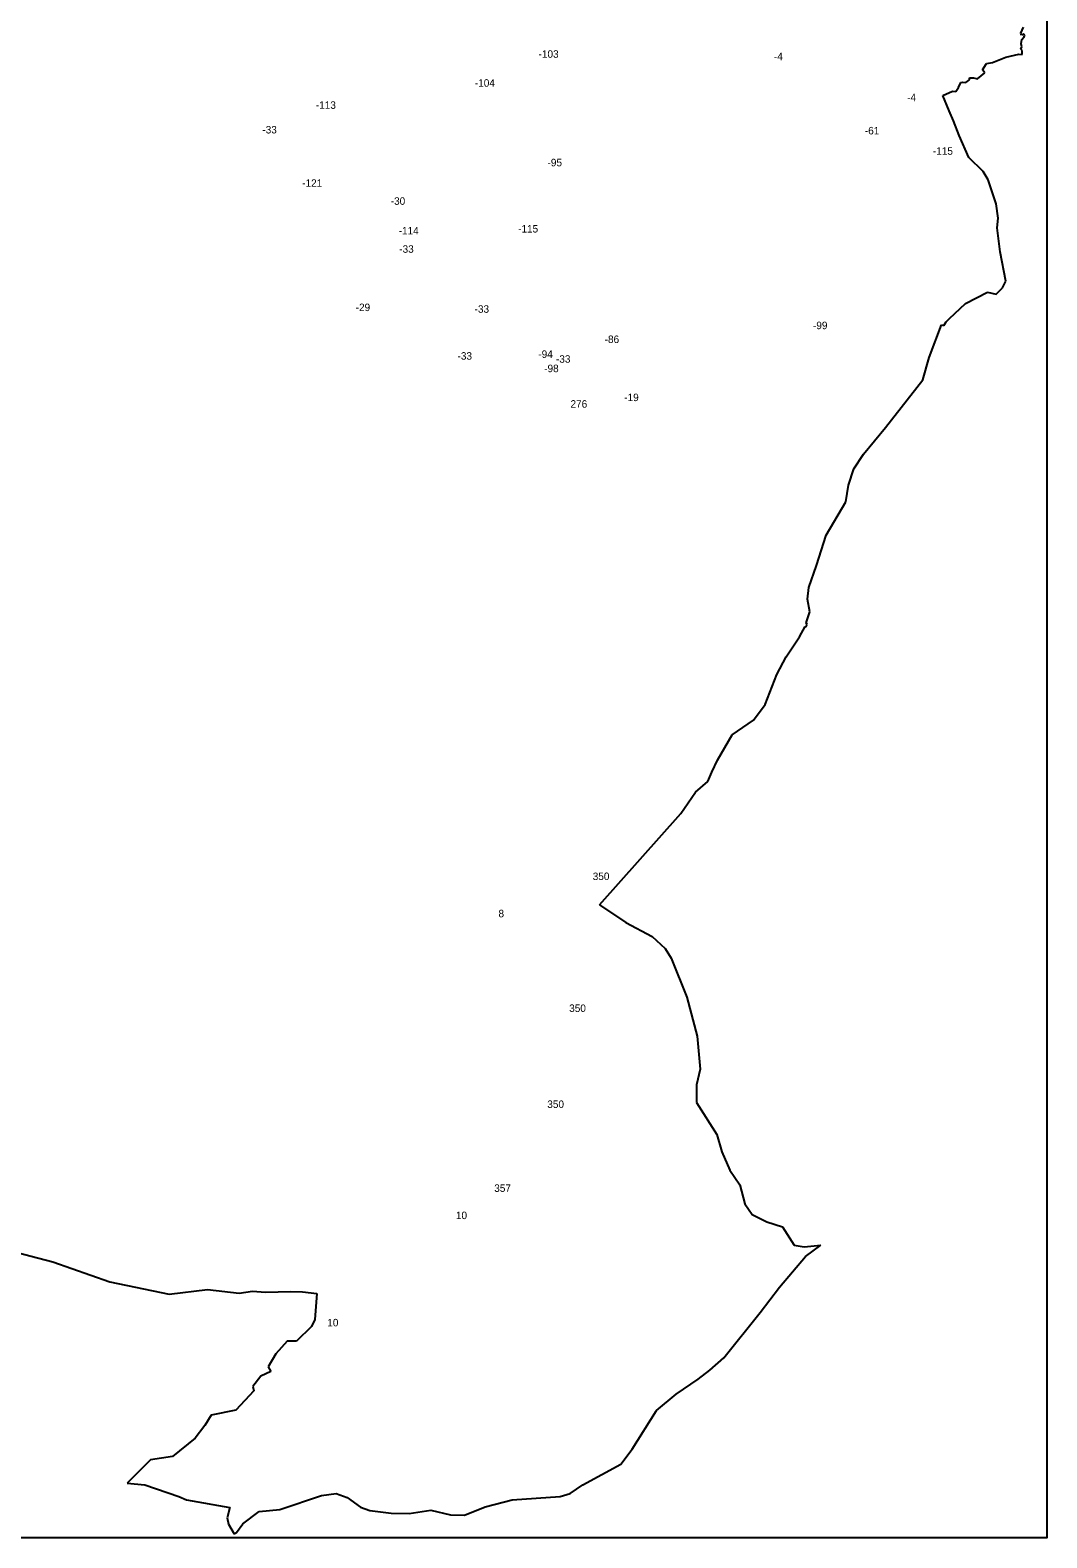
# Model space of a CAD drawing. Extents: x -780246 to -774760, y -968897 to -964868.
# Drawn here: x -776119 to -774760, y -968897 to -966883 of the extents above; entities that cross this region are included whole.
import ezdxf

# ---------------------------------------------------------------- set-up
doc = ezdxf.new("R2010")
doc.units = 0
doc.layers.add('Vrstva 13', color=7, linetype='Continuous')
doc.layers.add('Vrstva 15', color=7, linetype='Continuous')

msp = doc.modelspace()

# ---------------------------------------------------------------- linework, layer by layer
at = {"layer": 'Vrstva 13'}
for p, q in [((-774794.42, -966886.59), (-774790.84, -966878.64)), ((-774793.62, -966889.51), (-774794.42, -966886.59)), ((-774794.27, -966900.97), (-774793.32, -966895.27)), ((-774790.84, -966887.69), (-774793.62, -966889.51)), ((-774793.32, -966895.27), (-774790.04, -966891.63)), ((-774789.39, -966889.44), (-774790.84, -966887.69)), ((-774790.04, -966891.63), (-774789.39, -966889.44)), ((-774832.22, -966925.86), (-774814.75, -966918.84)), ((-774814.75, -966918.84), (-774797.32, -966914.92)), ((-774797.32, -966914.92), (-774792.6, -966915.31)), ((-774794.35, -966907.94), (-774793.37, -966905.09)), ((-774792.56, -966910.02), (-774794.35, -966907.94)), ((-774793.37, -966905.09), (-774794.27, -966900.97)), ((-774792.6, -966915.31), (-774792.56, -966910.02)), ((-774845.96, -966935.69), (-774840.26, -966927.36)), ((-774842.63, -966939.52), (-774845.96, -966935.69)), ((-774840.26, -966927.36), (-774832.22, -966925.86)), ((-774881.29, -966964.45), (-774877.92, -966959.44)), ((-774877.92, -966959.44), (-774874.75, -966952.64)), ((-774874.75, -966952.64), (-774872.33, -966952.06)), ((-774872.33, -966952.06), (-774868.09, -966952.64)), ((-774868.09, -966952.64), (-774863.31, -966948.84)), ((-774863.31, -966948.84), (-774863.2, -966946.32)), ((-774863.2, -966946.32), (-774857.94, -966946.18)), ((-774857.94, -966946.18), (-774852.49, -966947.57)), ((-774852.49, -966947.57), (-774842.63, -966939.52)), ((-774898.76, -966969.93), (-774885.97, -966964.01)), ((-774890.5, -966990.26), (-774898.76, -966969.93)), ((-774885.97, -966964.01), (-774881.29, -966964.45)), ((-774884.5, -967003.64), (-774890.5, -966990.26)), ((-774876.9, -967023.45), (-774884.5, -967003.64)), ((-774864.12, -967052.76), (-774876.9, -967023.45)), ((-774844.9, -967071.33), (-774864.12, -967052.76)), ((-774838.18, -967082.81), (-774844.9, -967071.33)), ((-774832.92, -967098.53), (-774838.18, -967082.81)), ((-774827.44, -967114.83), (-774832.92, -967098.53)), ((-774824.59, -967133.7), (-774827.44, -967114.83)), ((-774826.19, -967146.57), (-774824.59, -967133.7)), ((-774822.1, -967179.02), (-774826.19, -967146.57)), ((-774814.72, -967217.91), (-774822.1, -967179.02)), ((-774818.81, -967226.68), (-774814.72, -967217.91)), ((-774868.43, -967247.76), (-774838.94, -967232.78)), ((-774838.94, -967232.78), (-774827.44, -967235.16)), ((-774827.44, -967235.16), (-774818.81, -967226.68)), ((-774889.78, -967267.84), (-774868.43, -967247.76)), ((-774917.26, -967320.06), (-774900.35, -967276.51)), ((-774900.35, -967276.51), (-774897.46, -967277.03)), ((-774897.46, -967277.03), (-774894.35, -967272.37)), ((-774894.35, -967272.37), (-774889.78, -967267.84)), ((-774925.6, -967350), (-774917.26, -967320.06)), ((-774975.22, -967413.71), (-774925.6, -967350)), ((-775004.97, -967449.17), (-774975.22, -967413.71)), ((-775017.82, -967468.83), (-775004.97, -967449.17)), ((-775024.69, -967490.54), (-775017.82, -967468.83)), ((-775028.42, -967512.76), (-775024.69, -967490.54)), ((-775054.87, -967557.2), (-775028.42, -967512.76)), ((-775067.43, -967597.71), (-775054.87, -967557.2)), ((-775078.02, -967627.46), (-775067.43, -967597.71)), ((-775079.63, -967642.81), (-775078.02, -967627.46)), ((-775076.74, -967659.7), (-775079.63, -967642.81)), ((-775081.46, -967674.69), (-775076.74, -967659.7)), ((-775090.3, -967693.26), (-775082.92, -967679.22)), ((-775082.92, -967679.22), (-775082.04, -967680.1)), ((-775082.04, -967680.1), (-775080.07, -967676.81)), ((-775080.07, -967676.81), (-775081.46, -967674.69)), ((-775108.14, -967719.94), (-775090.3, -967693.26)), ((-775120.78, -967743.7), (-775108.14, -967719.94)), ((-775136.27, -967783.39), (-775120.78, -967743.7)), ((-775152.05, -967804.44), (-775136.27, -967783.39)), ((-775180.25, -967824.18), (-775152.05, -967804.44)), ((-775200.13, -967857.95), (-775180.25, -967824.18)), ((-775207.44, -967874.18), (-775200.13, -967857.95)), ((-775212.85, -967886.6), (-775207.44, -967874.18)), ((-775248.94, -967929.29), (-775229.22, -967900.64)), ((-775229.22, -967900.64), (-775212.85, -967886.6)), ((-775357.67, -968051.37), (-775248.94, -967929.29)), ((-775357.67, -968051.37), (-775322.35, -968074.89)), ((-775322.35, -968074.89), (-775287.37, -968093.76)), ((-775287.37, -968093.76), (-775270.02, -968109.48)), ((-775270.02, -968109.48), (-775261.98, -968122.35)), ((-775261.98, -968122.35), (-775241.07, -968174.78)), ((-775241.07, -968174.78), (-775227.04, -968226.54)), ((-775227.04, -968226.54), (-775223.1, -968270.99)), ((-775223.1, -968270.99), (-775227.85, -968291.61)), ((-775227.85, -968291.61), (-775228.14, -968315.3)), ((-775228.14, -968315.3), (-775200.95, -968358.29)), ((-775200.95, -968358.29), (-775194, -968381.24)), ((-775194, -968381.24), (-775183.62, -968405.81)), ((-775183.62, -968405.81), (-775170.1, -968425.32)), ((-775170.1, -968425.32), (-775163.49, -968450.62)), ((-775163.49, -968450.62), (-775153.58, -968464.95)), ((-775153.58, -968464.95), (-775134.14, -968474.75)), ((-775134.14, -968474.75), (-775113.24, -968481.7)), ((-775113.24, -968481.7), (-775097.31, -968506.19)), ((-775097.31, -968506.19), (-775084.15, -968508.09)), ((-775084.15, -968508.09), (-775061.95, -968506.01)), ((-775082.24, -968521.3), (-775061.95, -968506.01)), ((-776146.15, -968513.26), (-776088.5, -968528.4)), ((-776088.5, -968528.4), (-776012.08, -968554.78)), ((-775117.17, -968562.25), (-775082.24, -968521.3)), ((-776012.08, -968554.78), (-775932.67, -968571.36)), ((-775932.67, -968571.36), (-775881.52, -968565.22)), ((-775881.52, -968565.22), (-775839.37, -968569.91)), ((-775839.37, -968569.91), (-775821.69, -968567.57)), ((-775821.69, -968567.57), (-775804, -968568.66)), ((-775804, -968568.66), (-775770.1, -968568.07)), ((-775770.1, -968568.07), (-775754.65, -968568.4)), ((-775754.65, -968568.4), (-775735.54, -968570.55)), ((-775735.54, -968570.55), (-775738.32, -968605.42)), ((-775142.83, -968595.8), (-775117.17, -968562.25)), ((-775738.32, -968605.42), (-775742.79, -968614.76)), ((-775191.58, -968656.45), (-775142.83, -968595.8)), ((-775742.79, -968614.76), (-775762.59, -968634.21)), ((-775790.5, -968651.24), (-775800.37, -968668.71)), ((-775775.01, -968634.28), (-775790.5, -968651.24)), ((-775762.59, -968634.21), (-775775.01, -968634.28)), ((-775800.37, -968668.71), (-775796.86, -968674.93)), ((-775210.07, -968673.2), (-775191.58, -968656.45)), ((-775810.52, -968681.17), (-775821.01, -968694.73)), ((-775796.86, -968674.93), (-775810.52, -968681.17)), ((-775255.03, -968705.05), (-775225.64, -968685.16)), ((-775225.64, -968685.16), (-775210.07, -968673.2)), ((-775819.62, -968700.83), (-775843.7, -968726.31)), ((-775821.01, -968694.73), (-775819.62, -968700.83)), ((-775281.56, -968726.76), (-775255.03, -968705.05)), ((-775843.7, -968726.31), (-775876.93, -968733.03)), ((-775314.09, -968778.64), (-775281.56, -968726.76)), ((-775885.19, -968746.99), (-775898.05, -968763.81)), ((-775876.93, -968733.03), (-775885.19, -968746.99)), ((-775898.05, -968763.81), (-775928.44, -968788.44)), ((-775928.44, -968788.44), (-775958.04, -968792.61)), ((-775329.21, -968798.49), (-775314.09, -968778.64)), ((-775958.04, -968792.61), (-775989.16, -968823.97)), ((-775379.8, -968826.42), (-775329.21, -968798.49)), ((-775989.16, -968823.97), (-775965.27, -968826.23)), ((-775965.27, -968826.23), (-775919.97, -968841.98)), ((-775396.89, -968837.83), (-775379.8, -968826.42)), ((-775919.97, -968841.98), (-775909.92, -968846.29)), ((-775909.92, -968846.29), (-775851.91, -968856.39)), ((-775785.16, -968859.04), (-775729.09, -968840.47)), ((-775729.09, -968840.47), (-775709.65, -968837.91)), ((-775709.65, -968837.91), (-775694.92, -968843.03)), ((-775694.92, -968843.03), (-775677.3, -968855.86)), ((-775510.4, -968855.67), (-775474.3, -968846.03)), ((-775474.3, -968846.03), (-775410.27, -968841.78)), ((-775410.27, -968841.78), (-775396.89, -968837.83)), ((-775851.91, -968856.39), (-775855.42, -968870.07)), ((-775855.42, -968870.07), (-775853.44, -968878.62)), ((-775834.49, -968878.41), (-775812.42, -968861.82)), ((-775812.42, -968861.82), (-775785.16, -968859.04)), ((-775677.3, -968855.86), (-775664.63, -968860.41)), ((-775664.63, -968860.41), (-775635.97, -968864.16)), ((-775635.97, -968864.16), (-775612.14, -968864.31)), ((-775612.14, -968864.31), (-775583.09, -968860.25)), ((-775583.09, -968860.25), (-775556.82, -968866.21)), ((-775556.82, -968866.21), (-775538.21, -968866.64)), ((-775538.21, -968866.64), (-775510.4, -968855.67)), ((-775853.44, -968878.62), (-775845.91, -968891.78)), ((-775845.91, -968891.78), (-775843.04, -968889.97)), ((-775843.04, -968889.97), (-775834.49, -968878.41))]:
    msp.add_line(p, q, dxfattribs=at)
msp.add_lwpolyline([(-780246.31, -964867.52), (-774759.73, -964867.52), (-774759.73, -968897.03), (-780246.31, -968897.03)], close=True, dxfattribs=at)

# ---------------------------------------------------------------- texts
at = {"layer": 'Vrstva 15'}
for s, p in [('-103', (-775439.084, -966919.49)), ('-4', (-775124.536, -966922.73)), ('-104', (-775524.25, -966958.16)), ('-113', (-775736.799, -966987.71)), ('-4', (-774946.456, -966977.51)), ('-33', (-775808.28, -967020.63)), ('-61', (-775003.008, -967021.92)), ('-115', (-774912.049, -967049.11)), ('-95', (-775427.144, -967064.48)), ('-121', (-775755.019, -967091.89)), ('-30', (-775636.68, -967115.95)), ('-114', (-775626.025, -967155.53)), ('-115', (-775466.419, -967152.98)), ('-33', (-775625.31, -967180.04)), ('-29', (-775683.544, -967257.94)), ('-33', (-775524.61, -967260.2)), ('-99', (-775072.327, -967282.13)), ('-86', (-775350.744, -967300.62)), ('-33', (-775547.44, -967322.88)), ('-94', (-775439.43, -967320.53)), ('-33', (-775415.85, -967326.98)), ('-98', (-775431.584, -967339.57)), ('276', (-775396.418, -967387.03)), ('-19', (-775324.568, -967378.27)), ('350', (-775366.726, -968018.16)), ('8', (-775492.686, -968067.91)), ('350', (-775398.186, -968194.4)), ('350', (-775427.456, -968322.64)), ('357', (-775498.356, -968434.78)), ('10', (-775549.561, -968471.15)), ('10', (-775721.501, -968614.47))]:
    msp.add_text(s, height=10, dxfattribs=at).set_placement(p)

doc.saveas('drawing.dxf')
